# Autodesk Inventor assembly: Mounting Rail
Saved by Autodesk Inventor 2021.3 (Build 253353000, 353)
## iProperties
Created: 2023-01
Part Number: Mounting Rail
Document SubType Name: Assembly
Designer: AdminForWorker
Title: Mounting Rail v2
Author: AdminForWorker
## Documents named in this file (2)
- c:\worker\convert-fusion-r08-cosv3\tmp\job-1\200\output\files\2749a1aa-ae21-48fd-b796-1f1e71e29d9f\2353cfdd-084d-4a58-905d-541d448f2d6c.iam
- c:\worker\convert-fusion-r08-cosv3\tmp\job-1\200\output\files\2749a1aa-ae21-48fd-b796-1f1e71e29d9f\Alternate Mounting Rail.ipt
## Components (1 placed, 1 different names)
1. Alternate Mounting Rail:1
